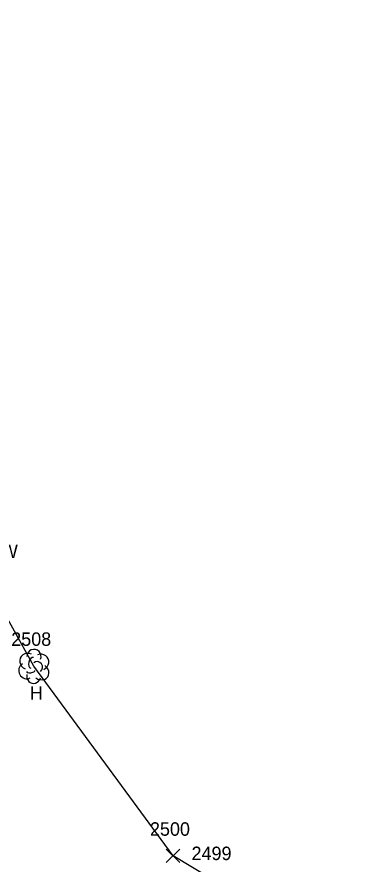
# Model space of a CAD drawing. Extents: x 1638344 to 1639591, y 610835 to 612202.
# Drawn here: x 1638966.6 to 1639017.2, y 611582.6 to 611708.6 of the extents above; entities that cross this region are included whole.
import ezdxf

# ---------------------------------------------------------------- set-up
doc = ezdxf.new("R2010")
doc.units = 0
for name, color, linetype in [('L_A', 7, 'Continuous'), ('L_I', 7, 'Continuous'), ('L_TIC', 7, 'Continuous'), ('LSOGP', 7, 'Continuous'), ('LTD', 7, 'Continuous')]:
    doc.layers.add(name, color=color, linetype=linetype)

msp = doc.modelspace()

# ---------------------------------------------------------------- linework, layer by layer
at = {"layer": 'L_TIC'}
for points in [[(1638988.8, 611582.83), (1638990.8, 611584.83)], [(1638990.8, 611582.83), (1638988.8, 611584.83)]]:
    msp.add_lwpolyline(points, dxfattribs=at)
at = {"layer": 'LSOGP'}
msp.add_lwpolyline([(1639180.86, 611428.14), (1639147.48, 611423.38), (1639131.91, 611444.98), (1639113.36, 611469.05), (1639093.12, 611490.67), (1639071.05, 611509.19), (1639055.5, 611526.42), (1639050.5, 611524.84), (1639039.27, 611539.22), (1639036.19, 611539.99), (1638995.83, 611580.21), (1638989.8, 611583.83), (1638969.06, 611612.07), (1638963.82, 611621.48), (1638962.78, 611633.12), (1638921.16, 611669.23), (1638917.31, 611673.07), (1638913.45, 611676.9), (1638906.9, 611682.61), (1638905.62, 611683.42), (1638890.13, 611696.93), (1638875.95, 611708.59)], dxfattribs=at)
at = {"layer": 'LTD'}
msp.add_line((1638969.06, 611612.07), (1638969.06, 611612.07), dxfattribs=at)
msp.add_line((1638969.06, 611612.07), (1638969.06, 611612.07), dxfattribs=at)
msp.add_arc((1638969.11, 611613.5), 1.05, 335.5272, 180.9563, dxfattribs=at)
for centre, major_axis, ratio, start_param, end_param in [((1638968.27, 611612.73), (1.21, -0.51), 0.895232, 1.570796, 4.712389), ((1638970.1, 611612.65), (-1.14, -0.48), 0.949671, 1.570796, 4.712389), ((1638967.98, 611611.36), (0.58, -1.04), 0.959034, 3.141593, 6.283185), ((1638968.85, 611612.53), (-0.208, -0.792), 0.645439, 3.141593, 6.283185), ((1638969.56, 611611.9), (-0.5, 0.667), 0.989748, 3.141593, 6.283185), ((1638968.6, 611611.32), (-0.625, -0.083), 0.423636, 0, 3.141593), ((1638970.06, 611611.23), (-1.09, 0.79), 0.841452, 1.570796, 4.712389), ((1638969.06, 611610.57), (0.26, 1.06), 0.942809, 1.570796, 4.712389)]:
    msp.add_ellipse(centre, major_axis=major_axis, ratio=ratio, start_param=start_param, end_param=end_param, dxfattribs=at)

# ---------------------------------------------------------------- texts
at = {"layer": 'L_A'}
for s, p in [('HOW', (1638960.17, 611628.12)), ('H', (1638968.49, 611607.07))]:
    msp.add_text(s, height=2, dxfattribs=at).set_placement(p)
at = {"layer": 'L_I'}
for s, p in [('2508', (1638965.72, 611615.07)), ('2500', (1638986.37, 611586.83)), ('2499', (1638992.56, 611583.21))]:
    msp.add_text(s, height=2, dxfattribs=at).set_placement(p)

doc.saveas('drawing.dxf')
